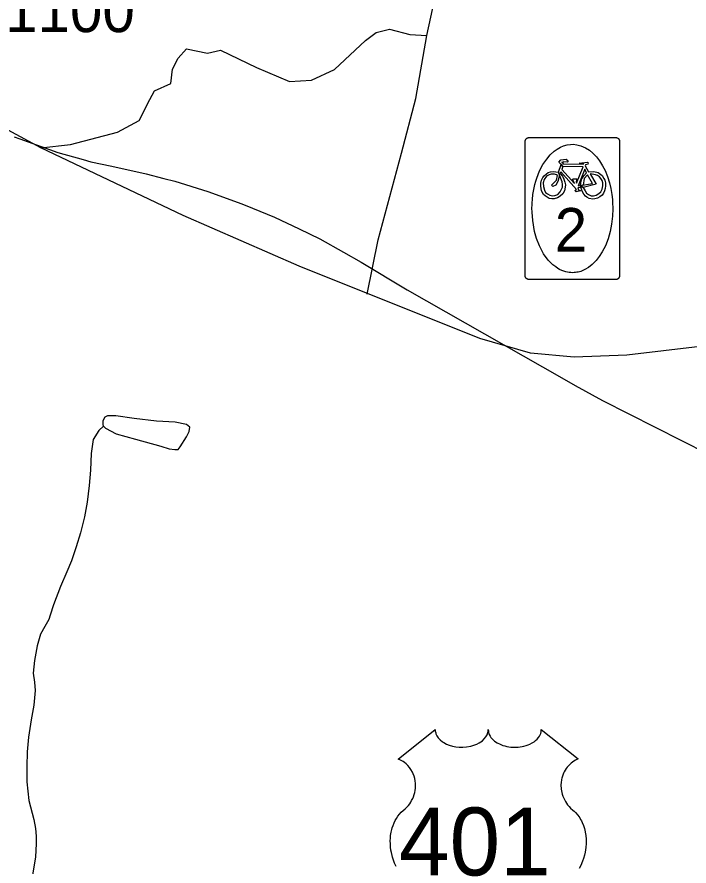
# Model space of a CAD drawing. Extents: x 2126262 to 2293712, y 749403 to 919119.
# Drawn here: x 2179353 to 2181281, y 811845 to 814282 of the extents above; entities that cross this region are included whole.
import ezdxf

# ---------------------------------------------------------------- set-up
doc = ezdxf.new("R2010")
doc.units = 0
for name, color, linetype in [('Exist Hydrographic Misc Water Feature', 7, 'Continuous'), ('Exist Road Non-System Type 51', 7, 'Continuous'), ('Exist Road Primary US Shield CELL', 7, 'Continuous'), ('Exist Road Primary US Shield Number Label', 7, 'Continuous'), ('Exist Road Secondary Bike CELL', 7, 'Continuous'), ('Exist Road Secondary Type 51 Attributed', 7, 'Continuous'), ('Exist Road Secondary Type 51 Number Label', 7, 'Continuous')]:
    doc.layers.add(name, color=color, linetype=linetype)

msp = doc.modelspace()

# ---------------------------------------------------------------- linework, layer by layer
at = {"layer": 'Exist Hydrographic Misc Water Feature'}
for p, q in [((2179344.8, 813938.4), (2179361.4, 813931.8)), ((2180915.5, 813245.8), (2180954.3, 813223.6))]:
    msp.add_line(p, q, dxfattribs=at)
for points in [[(2179361.4, 813931.8), (2179470.3, 813893.1), (2179543.1, 813872.7)], [(2179361.4, 813931.8), (2179470.3, 813893.1), (2179543.1, 813872.7)], [(2179543.1, 813872.7), (2179565.2, 813866.4), (2179625.1, 813853.3)], [(2179543.1, 813872.7), (2179565.2, 813866.4), (2179625.1, 813853.3)], [(2179625.1, 813853.3), (2179723.3, 813831.6), (2179774.6, 813818.6)], [(2179625.1, 813853.3), (2179723.3, 813831.6), (2179774.6, 813818.6)], [(2179774.6, 813818.6), (2179805.4, 813810.7), (2179900.1, 813781)], [(2179774.6, 813818.6), (2179805.4, 813810.7), (2179900.1, 813781)], [(2179900.1, 813781), (2179998.3, 813745.5), (2180028.9, 813733.1)], [(2179900.1, 813781), (2179998.3, 813745.5), (2180028.9, 813733.1)], [(2180028.9, 813733.1), (2180091.4, 813707.7), (2180162.3, 813673.7)], [(2180028.9, 813733.1), (2180091.4, 813707.7), (2180162.3, 813673.7)], [(2180162.3, 813673.7), (2180221.4, 813645.2), (2180289.7, 813606.6)], [(2180162.3, 813673.7), (2180221.4, 813645.2), (2180289.7, 813606.6)], [(2180289.7, 813606.6), (2180340.1, 813578.1), (2180472.4, 813498.9), (2180915.5, 813245.8)], [(2180289.7, 813606.6), (2180340.1, 813578.1), (2180472.4, 813498.9), (2180915.5, 813245.8)], [(2180954.3, 813223.6), (2181032.2, 813181.4), (2181334.4, 813027.8), (2181432.2, 812973.4), (2181508.3, 812925.4), (2181815.3, 812707.3), (2181866.3, 812669.1), (2181982.8, 812577.3)], [(2180954.3, 813223.6), (2181032.2, 813181.4), (2181334.4, 813027.8), (2181432.2, 812973.4), (2181508.3, 812925.4), (2181815.3, 812707.3), (2181866.3, 812669.1), (2181982.8, 812577.3)], [(2179601.5, 813107.2), (2179607.3, 813101.1), (2179637.2, 813085.2), (2179693.4, 813069.8), (2179765.8, 813049.9), (2179789.6, 813042.3), (2179805.8, 813040.2), (2179815.6, 813040.4), (2179821.6, 813048.4), (2179839.4, 813076.5), (2179847.2, 813092.4), (2179849.2, 813104.7), (2179839, 813112.3), (2179806.8, 813118.3), (2179753.1, 813122), (2179688.9, 813129.7), (2179637, 813137.1), (2179612.8, 813137.2), (2179604.8, 813133.1), (2179599.1, 813123), (2179599.1, 813111.2), (2179601.5, 813107.2)], [(2179601.5, 813107.2), (2179587.6, 813095.1), (2179571.8, 813069.1), (2179565.4, 813029.1), (2179563.8, 812981.1), (2179559.9, 812937), (2179554.6, 812889.2), (2179546.6, 812846.9), (2179535.1, 812800.8), (2179523, 812760.8), (2179509.1, 812720.8), (2179495.7, 812688.7), (2179478.1, 812646.7), (2179458, 812594.6), (2179448.2, 812564.4), (2179444, 812552.5), (2179432.6, 812532.3), (2179420.5, 812510.2), (2179411, 812476.3), (2179403.2, 812434.1), (2179399.3, 812398.2), (2179403, 812372.5), (2179405.5, 812348.2), (2179401.8, 812306.1), (2179394, 812264.3), (2179386, 812214.4), (2179382.5, 812172.3), (2179381.1, 812130.3), (2179380.9, 812086.1), (2179387.3, 812032.4), (2179401.6, 811978.3), (2179405.9, 811952.5), (2179407.8, 811930.3), (2179407.8, 811908.4), (2179406.1, 811870.5), (2179396.5, 811812.4)]]:
    msp.add_lwpolyline(points, dxfattribs=at)
at = {"layer": 'Exist Road Non-System Type 51'}
for points in [[(2180528.7, 814228.6), (2180556.6, 814357), (2180588.7, 814478.5)], [(2179421.1, 813906.3), (2179506.5, 813916), (2179641.8, 813951), (2179703.9, 813985.2), (2179734.6, 814045.2), (2179747.2, 814070.4), (2179794.6, 814091.3), (2179798.8, 814131.8), (2179815.5, 814163.9), (2179839.2, 814190.5), (2179899.2, 814177.9), (2179936.9, 814186.3), (2180040.2, 814137.4), (2180134.6, 814096.6), (2180197.4, 814100.8), (2180264.3, 814131.5), (2180352.9, 814214.6), (2180383.6, 814237), (2180421.3, 814246.7), (2180479.9, 814231.4), (2180528.7, 814228.6)], [(2180358, 813486.7), (2180389.2, 813642.1), (2180456.2, 813890.6), (2180497.3, 814047.7), (2180528.7, 814228.6)]]:
    msp.add_lwpolyline(points, dxfattribs=at)
at = {"layer": 'Exist Road Primary US Shield CELL'}
msp.add_lwpolyline([(2180440.4, 811843.3), (2180436.3, 811852.7), (2180433.2, 811861.3), (2180430.5, 811869.5), (2180429.1, 811874.7), (2180427.1, 811883.8), (2180425.9, 811890.2), (2180424.7, 811899.1), (2180424, 811908.5), (2180423.9, 811917.1), (2180424.1, 811924.2), (2180424.9, 811932.6), (2180426.4, 811941.4), (2180428.1, 811949), (2180429.6, 811954.5), (2180431.9, 811961.1), (2180434.8, 811968.5), (2180438.3, 811975.5), (2180441.7, 811981.4), (2180445.9, 811987.6), (2180450.1, 811993), (2180455.5, 811998.9), (2180461.1, 812004.3), (2180466.3, 812008.5), (2180472.5, 812014.5), (2180475.7, 812018.2), (2180479.5, 812023.2), (2180482.6, 812028), (2180485, 812032.2), (2180488.3, 812038.4), (2180490.2, 812043), (2180492.7, 812050.2), (2180493.9, 812055.2), (2180495.2, 812061.7), (2180496, 812067.8), (2180496.3, 812075.4), (2180496.1, 812081.7), (2180495.3, 812089), (2180493.9, 812096), (2180492.2, 812102.2), (2180489.6, 812109.2), (2180487.2, 812114.4), (2180483.1, 812121.3), (2180478.6, 812127.8), (2180473.9, 812133.1), (2180469.2, 812137.8), (2180464.7, 812141.3), (2180460.4, 812144.4), (2180455, 812147.7), (2180449.8, 812150.2), (2180446.5, 812151.5), (2180552.8, 812236.2), (2180553, 812231.8), (2180554.1, 812226.6), (2180554.9, 812223.9), (2180557.4, 812218.7), (2180561.4, 812212.7), (2180567, 812206.7), (2180573.4, 812201.5), (2180577.6, 812198.7), (2180584.9, 812194.8), (2180593.1, 812191.4), (2180602.3, 812188.7), (2180611.6, 812186.8), (2180621.8, 812185.7), (2180631.9, 812185.5), (2180642.9, 812186.3), (2180654.9, 812188.7), (2180660.5, 812190.1), (2180666.7, 812192.2), (2180672.5, 812194.6), (2180678.8, 812198), (2180683.9, 812201.3), (2180687.9, 812204.2), (2180693.6, 812209.6), (2180698, 812215.2), (2180699.9, 812218.3), (2180701.6, 812221.3), (2180703.8, 812227.7), (2180704.4, 812230.6), (2180704.9, 812236.4), (2180705.2, 812231.5), (2180705.7, 812228.4), (2180706.5, 812225.4), (2180707.8, 812222.2), (2180710.1, 812217.7), (2180712.6, 812213.9), (2180717.3, 812208.3), (2180720.3, 812205.6), (2180723, 812203.4), (2180730.2, 812198.4), (2180738.6, 812194.1), (2180742.8, 812192.3), (2180747, 812190.8), (2180752.4, 812189.2), (2180758, 812187.8), (2180763.5, 812186.9), (2180769.2, 812186.1), (2180775, 812185.6), (2180779.7, 812185.5), (2180785.4, 812185.6), (2180790.8, 812185.9), (2180796.2, 812186.5), (2180802.3, 812187.5), (2180807.1, 812188.6), (2180813.5, 812190.3), (2180819.3, 812192.4), (2180824.4, 812194.6), (2180830.9, 812198), (2180836.3, 812201.3), (2180840.2, 812204.5), (2180844.8, 812208.8), (2180849.2, 812213.8), (2180851.8, 812217.6), (2180853.6, 812221.4), (2180855.3, 812225.4), (2180856.3, 812229.7), (2180856.8, 812233.4), (2180856.9, 812236.5), (2180963.2, 812151.9), (2180960.7, 812150.9), (2180954.9, 812148.1), (2180950.4, 812145.4), (2180943, 812140.2), (2180939.9, 812137.4), (2180936.8, 812134.5), (2180933.9, 812131.3), (2180931.3, 812128.4), (2180928.3, 812124.1), (2180925.5, 812119.8), (2180922.8, 812115.1), (2180920.8, 812111), (2180917.6, 812102.5), (2180916, 812097.1), (2180915, 812092.5), (2180913.7, 812083), (2180913.4, 812078.5), (2180913.4, 812074.1), (2180913.7, 812069.3), (2180914.1, 812064.8), (2180914.9, 812060.1), (2180915.7, 812056), (2180917, 812050.9), (2180918.9, 812045), (2180921.2, 812039.3), (2180926.1, 812030), (2180932.3, 812020.6), (2180936.8, 812015.3), (2180941.2, 812010.8), (2180947.7, 812005.3), (2180951.3, 812002.1), (2180955.3, 811998.1), (2180962, 811990.3), (2180964.7, 811986.7), (2180967.4, 811982.6), (2180969.9, 811978.4), (2180972.5, 811973.9), (2180974.5, 811969.9), (2180978.2, 811960.8), (2180980.9, 811952), (2180982.2, 811947.3), (2180984.2, 811936.9), (2180984.9, 811931.7), (2180985.7, 811921.6), (2180985.8, 811909.3), (2180984.8, 811897.6), (2180982.6, 811884), (2180980.8, 811875.8), (2180978, 811866.3), (2180975.3, 811858.1), (2180970.4, 811846), (2180966.1, 811837.2)], dxfattribs=at)
at = {"layer": 'Exist Road Secondary Bike CELL'}
for points in [[(2180820.7, 813935.7), (2180821.5, 813935.8), (2180854.5, 813935.8), (2181037.9, 813935.8), (2181070.9, 813935.8), (2181072.1, 813935.7), (2181072.8, 813935.6), (2181073.5, 813935.4), (2181074.2, 813935.2), (2181074.9, 813934.9), (2181076.3, 813934.3), (2181076.9, 813933.9), (2181077.5, 813933.4), (2181078.2, 813932.8), (2181079.2, 813931.8), (2181079.8, 813931), (2181080.1, 813930.6), (2181080.3, 813930.2), (2181080.5, 813929.7), (2181080.7, 813929.3), (2181080.9, 813928.8), (2181081.2, 813928.1), (2181081.4, 813927.1), (2181081.6, 813926.2), (2181081.6, 813925.9), (2181081.6, 813925.5), (2181081.7, 813892), (2181081.7, 813572.1), (2181081.7, 813539), (2181081.6, 813537.9), (2181081.5, 813537.2), (2181081.3, 813536.5), (2181081.1, 813535.7), (2181080.8, 813535), (2181080.2, 813533.7), (2181079.8, 813533.1), (2181079.4, 813532.5), (2181078.7, 813531.8), (2181078.3, 813531.3), (2181077.7, 813530.8), (2181077.4, 813530.6), (2181076.9, 813530.2), (2181076.5, 813529.9), (2181076.1, 813529.7), (2181075.6, 813529.4), (2181074.7, 813529), (2181074, 813528.8), (2181073, 813528.6), (2181072.6, 813528.5), (2181072.1, 813528.4), (2181071.8, 813528.4), (2181071.4, 813528.3), (2181070.9, 813528.3), (2181037.8, 813528.3), (2180854.5, 813528.3), (2180821.5, 813528.3), (2180820.9, 813528.4), (2180820.4, 813528.4), (2180819.7, 813528.5), (2180819, 813528.7), (2180818.2, 813528.9), (2180817.5, 813529.1), (2180816.8, 813529.5), (2180816.2, 813529.8), (2180815.6, 813530.2), (2180815, 813530.6), (2180814.6, 813530.9), (2180814.2, 813531.2), (2180814, 813531.5), (2180813.6, 813532), (2180813.2, 813532.4), (2180812.9, 813532.8), (2180812.5, 813533.3), (2180812.3, 813533.7), (2180812, 813534.2), (2180811.7, 813534.8), (2180811.5, 813535.3), (2180811.4, 813535.6), (2180811.3, 813535.9), (2180811.2, 813536.1), (2180811.2, 813536.3), (2180811.1, 813536.6), (2180811.1, 813536.8), (2180811, 813537.1), (2180811, 813537.3), (2180810.9, 813537.6), (2180810.9, 813537.8), (2180810.9, 813538), (2180810.8, 813538.3), (2180810.8, 813538.9), (2180810.8, 813572.1), (2180810.8, 813892), (2180810.8, 813925), (2180810.9, 813926.2), (2180811, 813926.8), (2180811.2, 813927.6), (2180811.4, 813928.3), (2180811.6, 813929), (2180812.3, 813930.4), (2180812.7, 813931), (2180813.1, 813931.6), (2180813.7, 813932.3), (2180814.8, 813933.3), (2180815.6, 813933.9), (2180816, 813934.2), (2180816.4, 813934.4), (2180816.9, 813934.6), (2180817.3, 813934.8), (2180817.7, 813935), (2180818.5, 813935.3), (2180819.4, 813935.5), (2180820.3, 813935.7)], [(2180946.2, 813547.8), (2180941.6, 813548), (2180937.1, 813548.4), (2180927.2, 813550.1), (2180915.9, 813554.2), (2180909.4, 813557.4), (2180904.1, 813560.4), (2180898.4, 813564.3), (2180890.4, 813570.2), (2180876.7, 813584), (2180863.2, 813602.1), (2180851.4, 813625.2), (2180843.2, 813646), (2180837.9, 813666.5), (2180832.3, 813697.3), (2180830.4, 813721.7), (2180830.3, 813733.6), (2180830.5, 813742.3), (2180830.8, 813748.5), (2180831.4, 813757.8), (2180832.8, 813772.1), (2180835.5, 813786.7), (2180837.5, 813796.1), (2180838.8, 813801.4), (2180841.5, 813811), (2180844.1, 813819.5), (2180852, 813840), (2180861.8, 813858.5), (2180872.6, 813874.2), (2180882.1, 813885.9), (2180893.6, 813896.7), (2180902.5, 813902.6), (2180907.1, 813905.4), (2180912.4, 813908.2), (2180921, 813912.1), (2180931.3, 813914.8), (2180940.7, 813916.3), (2180948.4, 813916.5), (2180959.3, 813915.3), (2180970.6, 813912.2), (2180983.7, 813906.6), (2180994.9, 813899.7), (2181004.7, 813891.4), (2181015.3, 813880.4), (2181024.1, 813869), (2181032.6, 813855.1), (2181039.8, 813841.5), (2181046.9, 813824.3), (2181052.4, 813806.2), (2181056.4, 813789.2), (2181059.4, 813772.6), (2181061, 813758), (2181061.5, 813749.9), (2181062.4, 813730.9), (2181061.5, 813710.6), (2181058.8, 813687), (2181054.6, 813666.3), (2181048.7, 813645.4), (2181040.9, 813625.2), (2181031.8, 813607.7), (2181023.2, 813594.5), (2181014.4, 813583.1), (2181003.2, 813571.4), (2180992.8, 813563.1), (2180981.6, 813556.6), (2180970.2, 813551.7), (2180963, 813549.8), (2180958.9, 813549.1), (2180955.4, 813548.4), (2180951.6, 813548.1)], [(2180965.7, 813862.5), (2180989.8, 813865.4), (2180991.6, 813863.5), (2180990.2, 813859.8), (2180984.2, 813858), (2180982.6, 813854.7), (2180992.8, 813837.6), (2181007.3, 813838.3), (2181020.1, 813835.4), (2181031.4, 813826.9), (2181036.7, 813818.3), (2181039.3, 813813.7), (2181041.1, 813805.9), (2181041.5, 813797.7), (2181040.4, 813789.2), (2181038.6, 813782.7), (2181035, 813775.8), (2181031.5, 813770.6), (2181024.8, 813765.2), (2181018.7, 813761.6), (2181010.2, 813759.6), (2181004.9, 813759.3), (2180994.2, 813761), (2180987.3, 813764.5), (2180983.9, 813767.3), (2180978.8, 813773.8), (2180975.4, 813779.9), (2180970.7, 813792.1), (2180969.7, 813798), (2180977.1, 813792.7), (2180982.9, 813782.8), (2180987.1, 813776.1), (2180992.4, 813772.3), (2181000.5, 813769), (2181006.6, 813768.8), (2181014.8, 813770.6), (2181022.3, 813774.9), (2181027.7, 813780.2), (2181032, 813787.4), (2181033.4, 813797.4), (2181033.2, 813805.6), (2181031.4, 813812.3), (2181027.9, 813818.4), (2181024.2, 813822.7), (2181018.3, 813827.2), (2181012.6, 813829), (2181003.3, 813830.8), (2180996.8, 813831.5), (2181014.3, 813801.9), (2180977.1, 813792.7), (2180969.7, 813798), (2181003.9, 813804.1), (2180989.6, 813828.6), (2180979.8, 813818), (2180976.9, 813799.5), (2180969.7, 813798), (2180970.1, 813805.8), (2180973.2, 813817.6), (2180978.6, 813825.8), (2180986.4, 813834.7), (2180981.5, 813845.2), (2180962.7, 813797.3), (2180969.8, 813798), (2180970.7, 813792.1), (2180962.3, 813791.1), (2180964.1, 813785.9), (2180969.2, 813783.2), (2180956.6, 813780.4), (2180953.5, 813784.2), (2180958, 813786.7), (2180913.3, 813837.8), (2180911.6, 813832.9), (2180917.9, 813824.6), (2180922, 813816.6), (2180924.7, 813808), (2180926.2, 813800.6), (2180925.4, 813793.1), (2180923.3, 813783.2), (2180918.4, 813774.3), (2180911.5, 813767.5), (2180903.7, 813762.7), (2180894.1, 813760.4), (2180887.1, 813759.8), (2180880, 813760.7), (2180867.7, 813768.2), (2180863.7, 813772.8), (2180858, 813783.1), (2180855.5, 813796.1), (2180855.4, 813805.3), (2180857.7, 813813.5), (2180861.4, 813820.8), (2180865.5, 813826.1), (2180871.6, 813832.1), (2180876.9, 813835.4), (2180883.8, 813837.5), (2180890.8, 813838.2), (2180906.1, 813836.5), (2180909.6, 813828.2), (2180904.9, 813809.3), (2180898.8, 813799.3), (2180890, 813795.2), (2180886.5, 813798.7), (2180900.8, 813813.2), (2180903.9, 813826.9), (2180900.6, 813828.4), (2180894.7, 813830.3), (2180885.1, 813830.6), (2180879.6, 813828.9), (2180872.2, 813824.6), (2180865.1, 813815.3), (2180862, 813805.6), (2180863.3, 813794.9), (2180866, 813785), (2180869.5, 813778.5), (2180874.6, 813774.6), (2180881.8, 813770.1), (2180888.3, 813769), (2180896.3, 813769.5), (2180904.1, 813772.8), (2180910.9, 813779.6), (2180915.1, 813787.7), (2180917.6, 813793.5), (2180918.2, 813800.9), (2180917.2, 813808.8), (2180913.5, 813817.9), (2180906.1, 813836.5), (2180913.7, 813858.2), (2180919.2, 813852.5), (2180916.2, 813844), (2180951.8, 813804.1), (2180950.8, 813809.2), (2180947, 813815.5), (2180948.7, 813817), (2180958.9, 813817), (2180957, 813809.6), (2180958, 813804.5), (2180976.9, 813852.1), (2180919.2, 813852.5), (2180913.7, 813858.2), (2180907.1, 813865.3), (2180912.8, 813872), (2180928.1, 813874), (2180934.2, 813869.2), (2180930.9, 813864.9), (2180921.6, 813865.9), (2180915.3, 813864.5), (2180916.7, 813863.2), (2180919.9, 813863.2), (2180918.5, 813860), (2180977.7, 813859.5), (2180978.1, 813860.9)]]:
    msp.add_lwpolyline(points, close=True, dxfattribs=at)
at = {"layer": 'Exist Road Secondary Type 51 Attributed'}
msp.add_lwpolyline([(2182674.5, 812949.4), (2182121, 813222), (2181956.3, 813284.9), (2181708.7, 813361), (2181539.8, 813362.4), (2181102.4, 813311.4), (2180951.7, 813305.8), (2180826.2, 813317), (2180681.1, 813358.9), (2180162.7, 813566.3), (2179829.9, 813712.2), (2179421.1, 813906.3), (2179081.4, 814089.9), (2178937, 814202.4), (2178713.4, 814405.3), (2178495.2, 814581.5), (2178281.9, 814700.2), (2178134, 814800.7), (2178002.1, 814871.3), (2177546.6, 815088.4), (2177082.7, 815323), (2176680.5, 815537.7), (2176486.5, 815653.6), (2176402.8, 815727.6)], dxfattribs=at)

# ---------------------------------------------------------------- texts
at = {"layer": 'Exist Road Primary US Shield Number Label'}
msp.add_text('401', height=195, dxfattribs=at).set_placement((2180448.9, 811817.5))
at = {"layer": 'Exist Road Secondary Bike CELL'}
msp.add_text('2', height=125, dxfattribs=at).set_placement((2180895.6, 813608.6))
at = {"layer": 'Exist Road Secondary Type 51 Number Label'}
msp.add_text('1100', height=125, dxfattribs=at).set_placement((2179319.2, 814238.5))

doc.saveas('drawing.dxf')
